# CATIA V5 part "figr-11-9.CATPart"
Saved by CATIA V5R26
Part number: Part1
Bounding box of the stored display mesh (mm): x -50 to 50, y -39.834 to 41.856, z -25 to 25
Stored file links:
  D:\_Deepak\CATIA\CATIA V5-6R2016_Deepak\Resources\Part files\Partfiles\c11_catia_v5_6r2016_prt\figr-11-9.CATPart
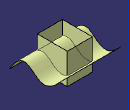
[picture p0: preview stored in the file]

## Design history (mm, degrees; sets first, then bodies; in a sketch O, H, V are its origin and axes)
Set1
  Sketch1 on yz-plane, origin (0, 0, 0), H (0, 1, 0), V (0, 0, 1)
    spline S1 through (-39.8338, -18.0686) (-4.7892, 0) (1.9431, -5.3632) (41.8556, 3.6938)
    point P1 (-4.7892, 0)
    coincidence: P1 H
  Extrude1: Element1 Sketch1, Lim1 50, Lim2 50, Direction yz-plane
  Sketch2 on xy-plane, origin (0, 0, 0), H (1, 0, 0), V (0, 1, 0)
    line L1 (-20.1634, 25.5896) -> (20.7534, 25.5896)
    line L2 (20.7534, 25.5896) -> (20.7534, -23.3463)
    line L3 (20.7534, -23.3463) -> (-20.1634, -23.3463)
    line L4 (-20.1634, -23.3463) -> (-20.1634, 25.5896)
    horizontal: L1 H, L3 H
    vertical: L2 V, L4 V
  Extrude2: Element1 Sketch2, Lim1 25, Lim2 25, Direction xy-plane
  Intersect1: ToIntersect1 Extrude1, ToIntersect2 Extrude2
Body1 (main body)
